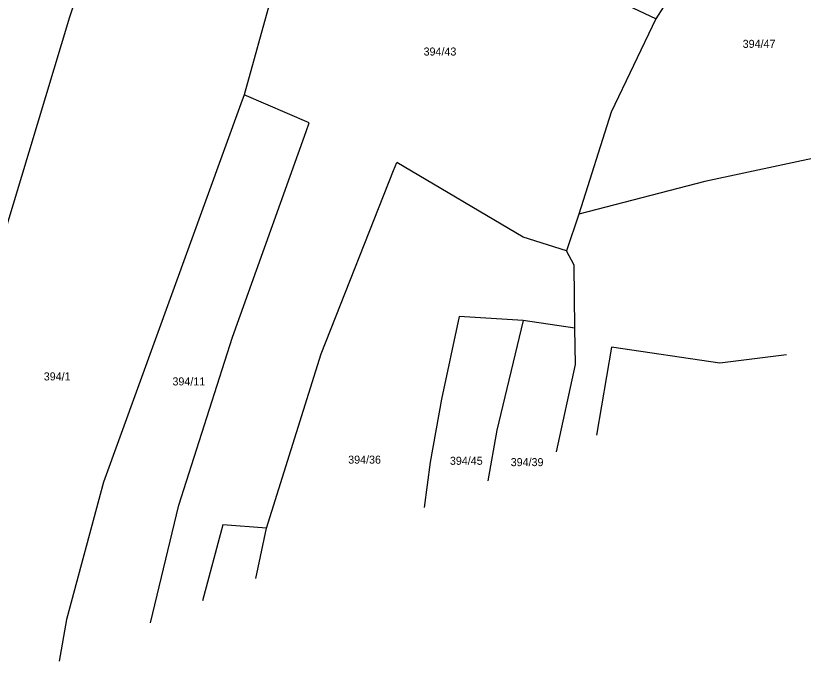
# Model space of a CAD drawing. Extents: x -680102 to -677253, y -1007548 to -1006096.
# Drawn here: x -677956 to -677710.2, y -1006886.5 to -1006685.2 of the extents above; entities that cross this region are included whole.
import ezdxf

# ---------------------------------------------------------------- set-up
doc = ezdxf.new("R2010")
doc.units = 0
doc.layers.add('1', color=7, linetype='Continuous', lineweight=25)
doc.layers.add('18', color=7, linetype='Continuous')

msp = doc.modelspace()

# ---------------------------------------------------------------- linework, layer by layer
at = {"layer": '1'}
for p, q in [((-677864.77, -1006638.19), (-677884.72, -1006709.85)), ((-677864.42, -1006718.61), (-677884.72, -1006709.85)), ((-677697.37, -1006727.51), (-677740.97, -1006736.82)), ((-677838.15, -1006733.39), (-677837.09, -1006730.95)), ((-677797.61, -1006754.27), (-677837.09, -1006730.95)), ((-677740.97, -1006736.82), (-677780.25, -1006747.08)), ((-677781.69, -1006762.98), (-677784.14, -1006758.51)), ((-677781.47, -1006782.67), (-677797.67, -1006780.27)), ((-677787.22, -1006821.2), (-677781.34, -1006793.96))]:
    msp.add_line(p, q, dxfattribs=at)
for points in [[(-677725.07, -1006637.34), (-677756.26, -1006686.07), (-677824.98, -1006653.66)], [(-677966.9, -1006777.33), (-677939.1, -1006685.51), (-677938.25, -1006682.71)], [(-677756.26, -1006686.07), (-677770.14, -1006715.19), (-677780.25, -1006747.08), (-677784.14, -1006758.51), (-677797.61, -1006754.27)], [(-677884.72, -1006709.85), (-677885.72, -1006712.6), (-677928.61, -1006830.69)], [(-677878.36, -1006757.56), (-677865.36, -1006721.24), (-677864.42, -1006718.61)], [(-677881.08, -1006860.71), (-677877.71, -1006845.04), (-677860.67, -1006790.63), (-677838.15, -1006733.39)], [(-677913.97, -1006874.55), (-677905.1, -1006837.86), (-677888.36, -1006785.41), (-677878.36, -1006757.56)], [(-677781.34, -1006793.96), (-677781.47, -1006782.67), (-677781.69, -1006762.98)], [(-677797.67, -1006780.27), (-677817.56, -1006778.94), (-677823.08, -1006804.79), (-677826.66, -1006824.38), (-677828.51, -1006838.58)], [(-677797.67, -1006780.27), (-677805.8, -1006814.45), (-677808.66, -1006830.22)], [(-677715.46, -1006790.99), (-677736.27, -1006793.51), (-677770.06, -1006788.55), (-677774.77, -1006815.96)], [(-677928.61, -1006830.69), (-677940.16, -1006873.49), (-677942.44, -1006886.54)], [(-677877.71, -1006845.04), (-677891.42, -1006843.94), (-677897.68, -1006867.69)]]:
    msp.add_lwpolyline(points, dxfattribs=at)

# ---------------------------------------------------------------- texts
at = {"layer": '18'}
for s, p in [('394/47', (-677729.11, -1006695.17)), ('394/43', (-677828.71, -1006697.57)), ('394/1', (-677947.27, -1006798.93)), ('394/11', (-677907.1, -1006800.49)), ('394/36', (-677852.25, -1006824.89)), ('394/45', (-677820.49, -1006825.25)), ('394/39', (-677801.52, -1006825.67))]:
    msp.add_text(s, height=2.5, dxfattribs=at).set_placement(p)

doc.saveas('drawing.dxf')
